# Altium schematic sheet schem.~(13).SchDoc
size A; SheetNumber: 1; SheetTotal: 1
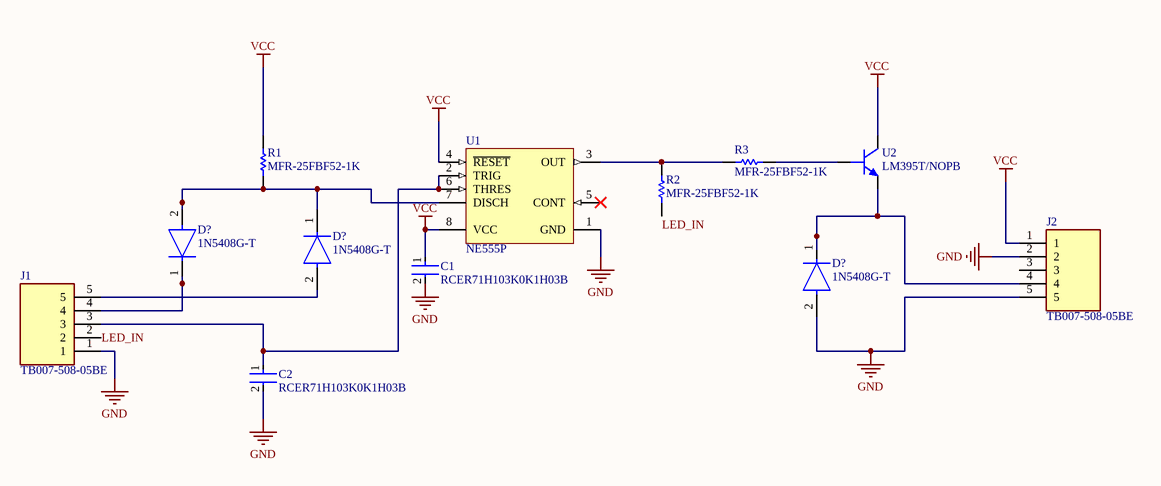
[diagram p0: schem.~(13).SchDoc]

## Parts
(Parts that share a designator on the sheet are numbered #1, #2 ... from top to bottom, then left to right.)
C1  RCER71H103K0K1H03B  [FP-RCE0K1-MFG]
C2  RCER71H103K0K1H03B  [FP-RCE0K1-MFG]
D?#1  1N5408G-T  [FP-DO-201AD-MFG]
D?#2  1N5408G-T  [FP-DO-201AD-MFG]
D?#3  1N5408G-T  [FP-DO-201AD-MFG]
J1  TB007-508-05BE  [CUI_TB007-508-05BE]
J2  TB007-508-05BE  [CUI_TB007-508-05BE]
R1  MFR-25FBF52-1K  [RESA60-630X240]
R2  MFR-25FBF52-1K  [RESA60-630X240]
R3  MFR-25FBF52-1K  [RESA60-630X240]
U1  NE555P  [P0008A]
U2  LM395T/NOPB  [NDE0003A]

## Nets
GND: C1.2 C2.2 D?#3.2(A) J1.1 J2.2 J2.5 U1.1(GND)
VCC: C1.1 J2.1 R1.2 U1.4(~{RESET}) U1.8(VCC) U2.3(C)
LED_IN: J1.2 R2.1
NetC2_1: C2.1 J1.3 U1.2(TRIG) U1.6(THRES)
NetD?#1_1: D?#1.1(C) J1.4
NetD?#1_2: D?#1.2(A) D?#2.1(C) R1.1 U1.7(DISCH)
NetD?#2_2: D?#2.2(A) J1.5
NetD?#3_1: D?#3.1(C) J2.4 U2.2(E)
NetR2_2: R2.2 R3.2 U1.3(OUT)
NetR3_1: R3.1 U2.1(B)

Not connected (* = marked no-connect by the designer): J2 3; U1 5(CONT)*

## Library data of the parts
C1 C2 = CMP-06035-044411-1: Cap Ceramic 10nF 50V X7R ±10% Radial 5mm +125°C Automotive Bulk; Lead/Base Style: Formed Leads; Lead Diameter: 0.5mm
D?#1-D?#3 = CMP-12791-000058-1: DIODE GEN PURP 1KV 3A DO201AD; Element Configuration: Single; Polarity: Standard; Max Reverse Current: 5uA; Reverse Recovery Time: 2us; Max Surge Current: 125A; Forward Voltage: 1.1V; Capacitance: 40pF
R1-R3 = CMP-1659-00075-1: Axial Resistor, 1 KOhm, +/- 1%, 250 mW, -55 to 155 degC, 2-Pin THD, RoHS, Bulk; Voltage Rating: 250 V; Resistance: 10 kohm; Power Rating: 250 mW
U1 = CMP-2000-04954-1: Precision Timer, 4.5 to 16 V, 0 to 70 degC, 8-Pin DIP, Pb-Free, Tube; Manufacturer: TexasInstruments; Maximum High Level Output Current: -200mA; Number of Internal Timers: 1; Operating Supply Voltage: 5; Maximum Low Level Output Current: 200mA; Rad Hard: No
U2 = CMP-0063-01416-3: Ultra Reliable Power Transistor, 3-pin TO-220, Pb-Free; Manufacturer: Texas Instruments; PowerWise: N; PackageTopMarking: NSUZXYTTE#*LM395T; CompType: MiscPower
